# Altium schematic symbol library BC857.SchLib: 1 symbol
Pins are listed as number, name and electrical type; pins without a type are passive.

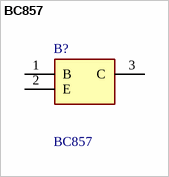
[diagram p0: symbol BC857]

## BC857
designator B?
Bipolar Transistors - BJT SOT23,PNP,0.1A,45V,L owNoise; Manufacturer_Name: Rectron; Geometry.Height: 1.15mm
footprint SOT95P240X115-3N
pins: 1 B, 2 E, 3 C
